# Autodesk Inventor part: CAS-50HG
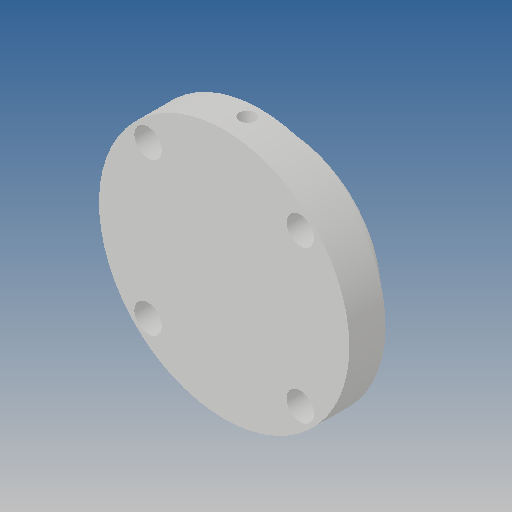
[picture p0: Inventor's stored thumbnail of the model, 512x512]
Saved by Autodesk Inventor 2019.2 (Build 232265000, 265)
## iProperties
Created: 2009-09
Part Number: CAS-50HG
Material: Ogólny
Document SubType Name: Modeling
Designer: CADENGINEERING4
Density: 1 g/cm^3
Appearance: Domyślna
Author: CADENGINEERING4
Revision Number: 1LAST_VERSION
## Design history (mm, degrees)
feature "Baza1"
node "Bryła1"
